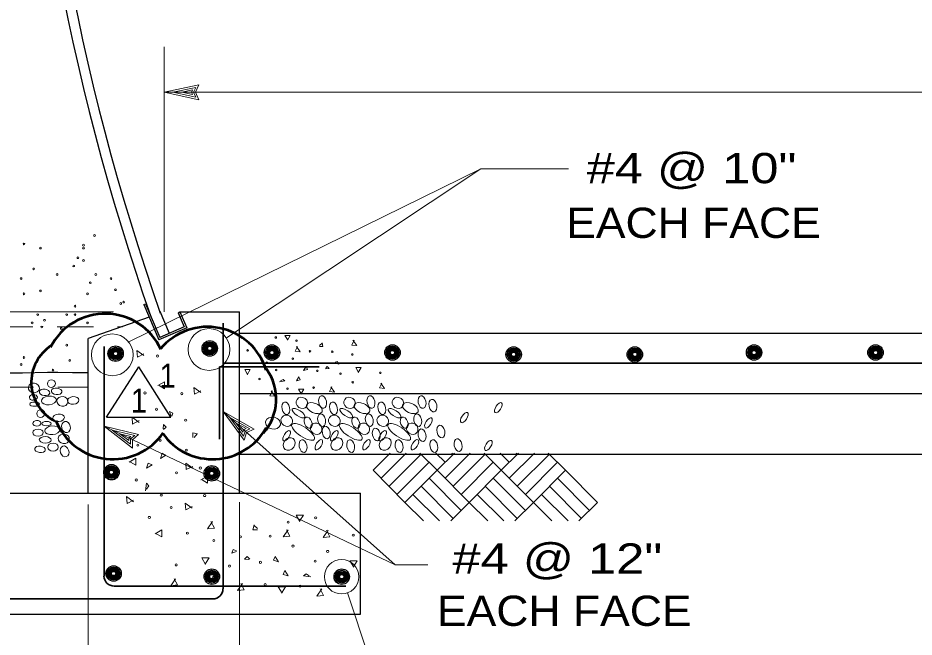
# Model space of a CAD drawing. Extents: x -24.3 to 17.7, y -17.6 to 12.4.
# Drawn here: x -16.992 to -13.287, y -12.611 to -10.053 of the extents above; entities that cross this region are included whole.
import ezdxf
from ezdxf.enums import TextEntityAlignment as Align

# ---------------------------------------------------------------- set-up
doc = ezdxf.new("R2010")
doc.units = 0
doc.header["$LTSCALE"] = 0.05
doc.linetypes.add('MEDIUM_DASHED', pattern=[4.5, 3, -1.5])
doc.layers.add('1', color=7, linetype='Continuous', lineweight=13)
doc.layers.add('2', color=7, linetype='Continuous', lineweight=13)

msp = doc.modelspace()

# ---------------------------------------------------------------- linework, layer by layer
at = {"layer": '1'}
for p, q in [((-16.38769, -11.2666), (-16.38769, -10.1726)), ((-16.38769, -10.3596), (-16.24369, -10.3286)), ((-16.38769, -10.3596), (-16.24369, -10.3906)), ((-16.35069, -10.3596), (-16.25669, -10.3396)), ((-16.35069, -10.3596), (-16.25669, -10.3796)), ((-16.31469, -10.3596), (-16.26969, -10.3496)), ((-16.31469, -10.3596), (-16.26969, -10.3686)), ((-16.26969, -10.3496), (-16.27369, -10.3596)), ((-16.27369, -10.3596), (-16.26969, -10.3686)), ((-16.25669, -10.3396), (-16.26569, -10.3596)), ((-16.26569, -10.3596), (-16.25669, -10.3796)), ((-15.07769, -10.6756), (-16.53369, -11.3916)), ((-15.07769, -10.6756), (-16.12969, -11.3746)), ((-15.07769, -10.6756), (-14.71569, -10.6756)), ((-16.59669, -11.2666), (-18.65469, -11.2666)), ((-15.43269, -12.3126), (-16.14369, -11.6786)), ((-16.14369, -11.6786), (-16.01569, -11.7516)), ((-16.14369, -11.6786), (-16.05669, -11.7976)), ((-16.11569, -11.7036), (-16.03269, -11.7506)), ((-16.11569, -11.7036), (-16.05969, -11.7806)), ((-15.43269, -12.3126), (-16.63569, -11.7396)), ((-16.63569, -11.7396), (-16.49269, -11.7736)), ((-16.63569, -11.7396), (-16.51869, -11.8296)), ((-16.08969, -11.7276), (-16.06169, -11.7636)), ((-16.08969, -11.7276), (-16.04869, -11.7496)), ((-16.60269, -11.7556), (-16.50869, -11.7776)), ((-16.60269, -11.7556), (-16.52569, -11.8136)), ((-16.56969, -11.7706), (-16.53269, -11.7986)), ((-16.56969, -11.7706), (-16.52469, -11.7816)), ((-16.50869, -11.7776), (-16.52569, -11.7916)), ((-16.05869, -11.7546), (-16.06169, -11.7636)), ((-16.05269, -11.7596), (-16.05969, -11.7806)), ((-16.04869, -11.7496), (-16.05869, -11.7546)), ((-16.03269, -11.7506), (-16.05269, -11.7596)), ((-16.52469, -11.7816), (-16.53269, -11.7886)), ((-16.53269, -11.7886), (-16.53269, -11.7986)), ((-16.52569, -11.7916), (-16.52569, -11.8136)), ((-15.52369, -11.9216), (-15.45269, -11.8506)), ((-15.49069, -11.9546), (-15.38669, -11.8506)), ((-15.25869, -11.9216), (-15.32969, -11.8506)), ((-15.22569, -11.8886), (-15.26369, -11.8506)), ((-15.25869, -11.9216), (-15.18769, -11.8506)), ((-15.25869, -11.9216), (-15.18769, -11.8506)), ((-15.22569, -11.9546), (-15.12169, -11.8506)), ((-15.19269, -11.8556), (-15.19769, -11.8506)), ((-14.99369, -11.9216), (-15.06469, -11.8506)), ((-14.96069, -11.8886), (-14.99869, -11.8506)), ((-14.99369, -11.9216), (-14.92269, -11.8506)), ((-14.96069, -11.9546), (-14.85569, -11.8506)), ((-14.92769, -11.8556), (-14.93169, -11.8506)), ((-14.72869, -11.9216), (-14.79969, -11.8506)), ((-15.45769, -11.9876), (-15.32469, -11.8556)), ((-15.42469, -12.0216), (-15.29169, -11.8886)), ((-15.19269, -11.9876), (-15.05969, -11.8556)), ((-15.15969, -12.0216), (-15.02669, -11.8886)), ((-14.92769, -11.9876), (-14.79469, -11.8556)), ((-14.89369, -12.0216), (-14.76169, -11.8886)), ((-15.39169, -12.0546), (-15.25869, -11.9216)), ((-15.12569, -12.0546), (-15.25869, -11.9216)), ((-15.12569, -12.0546), (-14.99369, -11.9216)), ((-14.86069, -12.0546), (-14.72869, -11.9216)), ((-14.59569, -12.0546), (-14.72869, -11.9216)), ((-15.15969, -12.0876), (-15.29169, -11.9546)), ((-14.89369, -12.0876), (-15.02669, -11.9546)), ((-14.62869, -12.0876), (-14.76169, -11.9546)), ((-15.19269, -12.1206), (-15.32469, -11.9876)), ((-14.92769, -12.1206), (-15.05969, -11.9876)), ((-14.66169, -12.1206), (-14.79469, -11.9876)), ((-15.24869, -12.1306), (-15.35869, -12.0216)), ((-14.98369, -12.1306), (-15.09269, -12.0216)), ((-14.71769, -12.1306), (-14.82769, -12.0216)), ((-16.70069, -13.6816), (-16.70069, -12.0626)), ((-16.07569, -14.4956), (-16.07569, -12.0536)), ((-15.20269, -12.1306), (-15.12569, -12.0546)), ((-15.04969, -12.1306), (-15.12569, -12.0546)), ((-14.93769, -12.1306), (-14.86069, -12.0546)), ((-14.67269, -12.1306), (-14.59569, -12.0546)), ((-15.43269, -12.3126), (-15.29669, -12.3126)), ((-15.39869, -13.1156), (-15.62969, -12.4286))]:
    msp.add_line(p, q, dxfattribs=at)
at = {"layer": '1', "lineweight": 25}
for p, q in [((-16.47169, -11.2366), (-16.46469, -11.2336)), ((-16.47169, -11.2366), (-16.40869, -11.3826)), ((-16.46469, -11.2336), (-16.40469, -11.3726)), ((-16.44969, -11.2886), (-16.70069, -11.3776)), ((-16.40569, -11.2646), (-16.36669, -11.3556)), ((-16.32969, -11.2706), (-16.32269, -11.2666)), ((-16.32369, -11.2666), (-16.07569, -11.2666)), ((-16.32269, -11.2666), (-16.29369, -11.3326)), ((-16.07569, -12.0166), (-16.07569, -11.2666)), ((-16.29369, -11.3326), (-16.40869, -11.3826)), ((-16.07569, -11.3546), (-3.74269, -11.3546)), ((-16.70069, -12.0166), (-16.70069, -11.3776)), ((-16.62493, -11.70276), (-16.49193, -11.49376)), ((-16.35893, -11.70276), (-16.49193, -11.49376)), ((-16.07569, -11.6046), (-3.74269, -11.6046)), ((-16.62493, -11.70276), (-16.35893, -11.70276)), ((-16.07569, -11.8546), (-3.74269, -11.8546)), ((-17.20069, -12.0166), (-15.57569, -12.0166))]:
    msp.add_line(p, q, dxfattribs=at)
at = {"layer": '1', "linetype": 'MEDIUM_DASHED'}
for p, q in [((-17.57969, -11.3286), (-16.55969, -11.3286)), ((-17.57669, -11.5786), (-16.69969, -11.5786))]:
    msp.add_line(p, q, dxfattribs=at)
at = {"layer": '1', "lineweight": 35}
for p, q in [((-16.14369, -12.4116), (-16.14369, -11.3136)), ((-16.63569, -12.3586), (-16.63569, -11.4106)), ((-16.13916, -11.4796), (-9.96569, -11.4796)), ((-15.74671, -11.49478), (-16.15797, -11.49478)), ((-16.15797, -11.79276), (-16.15797, -11.49478)), ((-15.63669, -12.4006), (-16.59369, -12.4006)), ((-16.18569, -12.4526), (-17.11869, -12.4526))]:
    msp.add_line(p, q, dxfattribs=at)
at = {"layer": '1'}
for points in [[(-16.24369, -10.3286), (-16.25769, -10.3596), (-16.24369, -10.3906)], [(-16.38769, -10.3596), (-9.90869, -10.3596), (-3.42969, -10.3596), (-3.57369, -10.3906)], [(-16.49269, -11.7736), (-16.51869, -11.7956), (-16.51869, -11.8296)], [(-16.01569, -11.7516), (-16.04669, -11.7656), (-16.05669, -11.7976)], [(-14.78469, -12.1306), (-14.99369, -11.9216), (-14.92269, -11.8506)], [(-15.31469, -12.1306), (-15.39169, -12.0546), (-15.52369, -11.9216)]]:
    msp.add_lwpolyline(points, dxfattribs=at)
at = {"layer": '1', "lineweight": 25}
for points in [[(-16.32969, -11.2706), (-16.30469, -11.3286), (-16.40469, -11.3726)], [(-17.06169, -11.5196), (-16.97269, -11.5196), (-16.86869, -11.5156), (-16.82669, -11.5156), (-16.76669, -11.5176), (-16.70069, -11.5176)], [(-17.20069, -12.5166), (-15.57569, -12.5166), (-15.57569, -12.0166)]]:
    msp.add_lwpolyline(points, dxfattribs=at)
at = {"layer": '1'}
for centre, radius in [((-16.67469, -10.9516), 0.00361), ((-16.96669, -10.9866), 0.00361), ((-16.89869, -11.0036), 0.00361), ((-16.72069, -10.9916), 0.00361), ((-16.72069, -11.0036), 0.00361), ((-16.76069, -11.0776), 0.00361), ((-16.74369, -11.0436), 0.00361), ((-16.72069, -11.0546), 0.00361), ((-16.92669, -11.0896), 0.00361), ((-16.82969, -11.1126), 0.00361), ((-16.66969, -11.1126), 0.00361), ((-16.97869, -11.1296), 0.00361), ((-16.69269, -11.1466), 0.00361), ((-16.60669, -11.1296), 0.00361), ((-16.89869, -11.1806), 0.00361), ((-16.58869, -11.1756), 0.00361), ((-16.96669, -11.1926), 0.00361), ((-16.70369, -11.1926), 0.00361), ((-16.55469, -11.2266), 0.00361), ((-16.75569, -11.2436), 0.00361), ((-16.56669, -11.2326), 0.00361), ((-16.90969, -11.2786), 0.00361), ((-16.88169, -11.3016), 0.00361), ((-16.78969, -11.2786), 0.00361), ((-16.75569, -11.2786), 0.00361), ((-16.93269, -11.3126), 0.00361), ((-16.89269, -11.3296), 0.00361), ((-16.81269, -11.3356), 0.00361), ((-16.70369, -11.3126), 0.00361), ((-16.60169, -11.4446), 0.08613), ((-16.20169, -11.4226), 0.08613), ((-16.78969, -11.4046), 0.00361), ((-16.97869, -11.4846), 0.00361), ((-16.96669, -11.4556), 0.00361), ((-16.77769, -11.4676), 0.00361), ((-16.84669, -11.5076), 0.00361), ((-15.65369, -12.3616), 0.0712)]:
    msp.add_circle(centre, radius, dxfattribs=at)
at = {"layer": '1', "lineweight": 25}
for centre, radius in [((-16.58797, -11.43969), 0.0319), ((-16.19865, -11.41821), 0.0319), ((-16.19865, -11.41821), 0.02658), ((-16.19865, -11.41821), 0.02215), ((-16.19865, -11.41821), 0.01846), ((-16.19865, -11.41821), 0.01538), ((-16.19865, -11.41821), 0.01282), ((-16.19865, -11.41821), 0.01068), ((-16.19865, -11.41821), 0.0089), ((-15.94149, -11.43513), 0.0319), ((-15.94149, -11.43513), 0.02658), ((-15.44351, -11.43513), 0.0319), ((-15.44351, -11.43513), 0.02658), ((-13.94856, -11.43513), 0.0319), ((-13.94856, -11.43513), 0.02658), ((-13.44657, -11.43513), 0.0319), ((-13.44657, -11.43513), 0.02658), ((-16.58797, -11.43969), 0.02658), ((-16.58797, -11.43969), 0.02215), ((-16.58797, -11.43969), 0.01846), ((-16.58797, -11.43969), 0.01538), ((-16.58797, -11.43969), 0.01282), ((-16.58797, -11.43969), 0.01068), ((-16.58797, -11.43969), 0.0089), ((-15.94149, -11.43513), 0.02215), ((-15.94149, -11.43513), 0.01846), ((-15.94149, -11.43513), 0.01538), ((-15.94149, -11.43513), 0.01282), ((-15.94149, -11.43513), 0.01068), ((-15.94149, -11.43513), 0.0089), ((-15.44351, -11.43513), 0.02215), ((-15.44351, -11.43513), 0.01846), ((-15.44351, -11.43513), 0.01538), ((-15.44351, -11.43513), 0.01282), ((-15.44351, -11.43513), 0.01068), ((-15.44351, -11.43513), 0.0089), ((-14.94253, -11.44313), 0.0319), ((-14.94253, -11.44313), 0.02658), ((-14.94253, -11.44313), 0.02215), ((-14.94253, -11.44313), 0.01846), ((-14.94253, -11.44313), 0.01538), ((-14.94253, -11.44313), 0.01282), ((-14.94253, -11.44313), 0.01068), ((-14.94253, -11.44313), 0.0089), ((-14.44154, -11.44313), 0.0319), ((-14.44154, -11.44313), 0.02658), ((-14.44154, -11.44313), 0.02215), ((-14.44154, -11.44313), 0.01846), ((-14.44154, -11.44313), 0.01538), ((-14.44154, -11.44313), 0.01282), ((-14.44154, -11.44313), 0.01068), ((-14.44154, -11.44313), 0.0089), ((-13.94856, -11.43513), 0.02215), ((-13.94856, -11.43513), 0.01846), ((-13.94856, -11.43513), 0.01538), ((-13.94856, -11.43513), 0.01282), ((-13.94856, -11.43513), 0.01068), ((-13.94856, -11.43513), 0.0089), ((-13.44657, -11.43513), 0.02215), ((-13.44657, -11.43513), 0.01846), ((-13.44657, -11.43513), 0.01538), ((-13.44657, -11.43513), 0.01282), ((-13.44657, -11.43513), 0.01068), ((-13.44657, -11.43513), 0.0089), ((-16.60497, -11.92969), 0.0319), ((-16.60497, -11.92969), 0.02658), ((-16.60497, -11.92969), 0.02215), ((-16.60497, -11.92969), 0.01846), ((-16.60497, -11.92969), 0.01538), ((-16.60497, -11.92969), 0.01282), ((-16.60497, -11.92969), 0.01068), ((-16.60497, -11.92969), 0.0089), ((-16.19032, -11.93444), 0.0319), ((-16.19032, -11.93444), 0.02658), ((-16.19032, -11.93444), 0.02215), ((-16.19032, -11.93444), 0.01846), ((-16.19032, -11.93444), 0.01538), ((-16.19032, -11.93444), 0.01282), ((-16.19032, -11.93444), 0.01068), ((-16.19032, -11.93444), 0.0089), ((-16.59622, -12.34818), 0.0319), ((-16.59622, -12.34818), 0.02658), ((-16.59622, -12.34818), 0.02215), ((-16.59622, -12.34818), 0.01846), ((-16.59622, -12.34818), 0.01538), ((-16.59622, -12.34818), 0.01282), ((-16.19007, -12.3611), 0.0319), ((-16.19007, -12.3611), 0.02658), ((-15.65309, -12.36135), 0.0319), ((-15.65309, -12.36135), 0.02658), ((-16.59622, -12.34818), 0.01068), ((-16.59622, -12.34818), 0.0089), ((-16.19007, -12.3611), 0.02215), ((-16.19007, -12.3611), 0.01846), ((-16.19007, -12.3611), 0.01538), ((-16.19007, -12.3611), 0.01282), ((-16.19007, -12.3611), 0.01068), ((-16.19007, -12.3611), 0.0089), ((-15.65309, -12.36135), 0.02215), ((-15.65309, -12.36135), 0.01846), ((-15.65309, -12.36135), 0.01538), ((-15.65309, -12.36135), 0.01282), ((-15.65309, -12.36135), 0.01068), ((-15.65309, -12.36135), 0.0089)]:
    msp.add_circle(centre, radius, dxfattribs=at)
for radius in [9.74984, 9.70818]:
    msp.add_arc((-7.24244, -8.05836), radius, 180.86487, 199.33073, dxfattribs=at)
at = {"layer": '1', "lineweight": 53}
for centre, radius, start, end in [((-16.63089, -11.52803), 0.25334, 24.55974, 152.92582), ((-16.20764, -11.58231), 0.25334, 16.99373, 140.21229), ((-16.75642, -11.55812), 0.18009, 122.74739, 242.84867), ((-16.13663, -11.62787), 0.21291, 318.5024, 35.87306), ((-16.59928, -11.62262), 0.25334, 201.68598, 325.30294), ((-16.18689, -11.62262), 0.25334, 215.44791, 330.66798)]:
    msp.add_arc(centre, radius, start, end, dxfattribs=at)
at = {"layer": '1', "lineweight": 35}
for centre, start, end in [((-16.59416, -12.35863), 180, 270), ((-16.18575, -12.41133), 270, 0)]:
    msp.add_arc(centre, 0.04167, start, end, dxfattribs=at)
at = {"layer": '1'}
for centre, major_axis, ratio in [((-16.85327, -11.56354), (0.01537, 0.00658), 0.943549), ((-16.92573, -11.58115), (0.02279, -0.0031), 0.872178), ((-16.88127, -11.59977), (0.02175, -0.0031), 0.60385), ((-16.83156, -11.59565), (0.02175, -0.0031), 0.60385), ((-16.92783, -11.62052), (0.01656, 0.00102), 0.695424), ((-16.86366, -11.63294), (0.03106, 0.0031), 0.576005), ((-16.80773, -11.63706), (0.02279, -0.0031), 0.872178), ((-16.76323, -11.63294), (-0.024, -0.00161), 0.646571), ((-15.81769, -11.6431), (-0.02021, 0.0142), 0.915279), ((-15.73219, -11.6396), (-0.0055, 0.026), 0.599528), ((-15.62069, -11.6431), (-0.02021, 0.0142), 0.915279), ((-15.53219, -11.6396), (-0.0055, 0.026), 0.599528), ((-15.42069, -11.6431), (-0.02021, 0.0142), 0.915279), ((-15.32119, -11.6396), (-0.0055, 0.026), 0.599528), ((-15.27619, -11.6546), (-0.0055, 0.026), 0.599528), ((-16.92264, -11.64846), (0.01967, 0), 0.453554), ((-15.88419, -11.6656), (-0.0055, 0.026), 0.599528), ((-15.83169, -11.6856), (-0.026, 0.017), 0.365968), ((-15.76619, -11.6646), (-0.0315, 0.015), 0.562188), ((-15.68719, -11.6656), (-0.0055, 0.026), 0.599528), ((-15.63469, -11.6856), (-0.026, 0.017), 0.365968), ((-15.56919, -11.6646), (-0.0315, 0.015), 0.562188), ((-15.48719, -11.6656), (-0.0055, 0.026), 0.599528), ((-15.43469, -11.6856), (-0.026, 0.017), 0.365968), ((-15.36919, -11.6646), (-0.0315, 0.015), 0.562188), ((-15.00569, -11.6631), (0.013, 0.0205), 0.445558), ((-16.89718, -11.68714), (0.01537, 0.00658), 0.943549), ((-16.82369, -11.70474), (-0.024, -0.00161), 0.646571), ((-15.93719, -11.7266), (-0.03038, 0.00696), 0.790099), ((-15.88069, -11.7171), (-0.02021, 0.0142), 0.915279), ((-15.79169, -11.7251), (-0.009, 0.0225), 0.615421), ((-15.73619, -11.7146), (-0.0055, 0.026), 0.599528), ((-15.68369, -11.7171), (-0.02021, 0.0142), 0.915279), ((-15.59469, -11.7251), (-0.009, 0.0225), 0.615421), ((-15.53919, -11.7146), (-0.0055, 0.026), 0.599528), ((-15.48369, -11.7171), (-0.02021, 0.0142), 0.915279), ((-15.39469, -11.7251), (-0.009, 0.0225), 0.615421), ((-15.33919, -11.7146), (-0.0055, 0.026), 0.599528), ((-15.29469, -11.7261), (0.013, 0.0205), 0.445558), ((-15.14669, -11.7041), (0.013, 0.0205), 0.445558), ((-16.91375, -11.72753), (0.01656, 0.00102), 0.695424), ((-16.87339, -11.72855), (0.01967, 0), 0.453554), ((-16.84958, -11.75653), (0.03106, 0.0031), 0.576005), ((-16.79262, -11.74305), (0.00519, -0.02279), 0.773526), ((-15.81269, -11.7631), (-0.04615, 0.03077), 0.357541), ((-15.75869, -11.7501), (-0.02021, 0.0142), 0.915279), ((-15.71719, -11.7656), (-0.0055, 0.026), 0.599528), ((-15.61569, -11.7631), (-0.04615, 0.03077), 0.357541), ((-15.56169, -11.7501), (-0.02021, 0.0142), 0.915279), ((-15.41569, -11.7631), (-0.04615, 0.03077), 0.357541), ((-15.36169, -11.7501), (-0.02021, 0.0142), 0.915279), ((-15.24319, -11.7616), (-0.0055, 0.026), 0.599528), ((-16.90858, -11.76585), (0.02173, 0), 0.668043), ((-16.80194, -11.7917), (0.02279, -0.0031), 0.872178), ((-15.88069, -11.7791), (0.013, 0.0205), 0.445558), ((-15.68369, -11.7791), (0.013, 0.0205), 0.445558), ((-15.51019, -11.7736), (-0.0055, 0.026), 0.599528), ((-15.48369, -11.7791), (0.013, 0.0205), 0.445558), ((-15.32119, -11.7766), (-0.0055, 0.026), 0.599528), ((-16.87856, -11.79584), (0.02483, -0.00104), 0.540552), ((-16.84646, -11.82589), (0.02173, 0), 0.771092), ((-15.87019, -11.8131), (0.0165, 0.0225), 0.822116), ((-15.81319, -11.8216), (-0.0055, 0.026), 0.599528), ((-15.74769, -11.8161), (0.013, 0.0205), 0.445558), ((-15.67319, -11.8131), (0.0165, 0.0225), 0.822116), ((-15.61619, -11.8216), (-0.0055, 0.026), 0.599528), ((-15.55069, -11.8161), (0.013, 0.0205), 0.445558), ((-15.47319, -11.8131), (0.0165, 0.0225), 0.822116), ((-15.41619, -11.8216), (-0.0055, 0.026), 0.599528), ((-15.35069, -11.8161), (0.013, 0.0205), 0.445558), ((-15.27219, -11.8216), (-0.0055, 0.026), 0.599528), ((-15.17219, -11.8176), (-0.0055, 0.026), 0.599528), ((-15.04669, -11.8191), (0.013, 0.0205), 0.445558), ((-16.90031, -11.8352), (0.02175, -0.0031), 0.60385), ((-16.79885, -11.84349), (0.00725, -0.02173), 0.776129)]:
    msp.add_ellipse(centre, major_axis=major_axis, ratio=ratio, dxfattribs=at)
at = {"layer": '2'}
for p, q in [((-15.74569, -11.4066), (-15.73469, -11.3966)), ((-16.26369, -11.7866), (-16.25069, -11.7706)), ((-16.00069, -12.1626), (-16.01569, -12.1496))]:
    msp.add_line(p, q, dxfattribs=at)
for points in [[(-15.87769, -11.3816), (-15.88769, -11.3646), (-15.86569, -11.3646), (-15.87769, -11.3846)], [(-15.73469, -11.3946), (-15.73069, -11.4096), (-15.74569, -11.4096)], [(-15.60169, -11.3846), (-15.61169, -11.4046), (-15.59069, -11.4066), (-15.60669, -11.3846)], [(-16.47069, -11.4406), (-16.49769, -11.4546), (-16.49969, -11.4266), (-16.47069, -11.4476)], [(-15.95969, -11.4116), (-15.96969, -11.4316), (-15.94969, -11.4336), (-15.96469, -11.4116)], [(-15.83569, -11.4096), (-15.84569, -11.4296), (-15.82469, -11.4316), (-15.84069, -11.4096)], [(-15.68069, -11.4756), (-15.67069, -11.4716), (-15.66569, -11.4826), (-15.68069, -11.4776)], [(-16.04369, -11.5226), (-16.05369, -11.5056), (-16.03169, -11.5056), (-16.04369, -11.5266)], [(-15.72069, -11.5006), (-15.71369, -11.4926), (-15.70569, -11.5006), (-15.71869, -11.5026)], [(-15.58469, -11.5146), (-15.59469, -11.4976), (-15.57269, -11.4976), (-15.58469, -11.5176)], [(-16.40769, -11.5716), (-16.38569, -11.5846), (-16.38569, -11.5556), (-16.41269, -11.5716)], [(-15.90569, -11.5526), (-15.89569, -11.5466), (-15.88769, -11.5526), (-15.91069, -11.5566)], [(-16.23569, -11.5936), (-16.26169, -11.6066), (-16.26469, -11.5796), (-16.23569, -11.6006)], [(-15.93969, -11.5936), (-15.94969, -11.6136), (-15.92969, -11.6156), (-15.94469, -11.5936)], [(-15.82169, -11.6036), (-15.83169, -11.5866), (-15.80969, -11.5866), (-15.82169, -11.6066)], [(-15.69369, -11.5766), (-15.70369, -11.5966), (-15.68369, -11.5986), (-15.69869, -11.5766)], [(-15.48669, -11.5616), (-15.49669, -11.5816), (-15.47669, -11.5836), (-15.49169, -11.5616)], [(-16.49069, -11.7166), (-16.51769, -11.7306), (-16.51969, -11.7026), (-16.49069, -11.7236)], [(-16.35569, -11.6986), (-16.35169, -11.6856), (-16.36569, -11.6786), (-16.35869, -11.6986)], [(-16.38969, -11.7526), (-16.37869, -11.7436), (-16.38969, -11.7326), (-16.39169, -11.7506)], [(-16.24869, -11.7706), (-16.26869, -11.7666), (-16.26869, -11.7866)], [(-16.52669, -11.8876), (-16.50369, -11.9006), (-16.50369, -11.8716), (-16.53169, -11.8876)], [(-16.26869, -11.9056), (-16.29569, -11.9186), (-16.29769, -11.8916), (-16.26869, -11.9126)], [(-16.23069, -11.9616), (-16.20769, -11.9746), (-16.20769, -11.9456), (-16.23569, -11.9616)], [(-16.45969, -11.9996), (-16.45069, -11.9866), (-16.45969, -11.9746), (-16.46369, -12.0066)], [(-16.51369, -12.0446), (-16.53969, -12.0586), (-16.54269, -12.0306), (-16.51369, -12.0516)], [(-16.27169, -12.0716), (-16.29769, -12.0846), (-16.30069, -12.0576), (-16.27169, -12.0786)], [(-15.82569, -12.1296), (-15.81169, -12.1066), (-15.84169, -12.1066), (-15.82569, -12.1336)], [(-16.19369, -12.1336), (-16.17969, -12.1606), (-16.20769, -12.1636), (-16.18669, -12.1336)], [(-16.01569, -12.1476), (-16.02069, -12.1676), (-16.00069, -12.1676)], [(-16.41969, -12.1836), (-16.39669, -12.1966), (-16.39669, -12.1676), (-16.42369, -12.1836)], [(-15.88169, -12.1676), (-15.86769, -12.1936), (-15.89569, -12.1966), (-15.87469, -12.1676)], [(-15.71569, -12.1696), (-15.70169, -12.1966), (-15.72969, -12.1996), (-15.70869, -12.1696)], [(-16.08769, -12.2546), (-16.10169, -12.2496), (-16.10769, -12.2636), (-16.08769, -12.2576)], [(-16.21569, -12.3066), (-16.20169, -12.2836), (-16.23169, -12.2836), (-16.21569, -12.3116)], [(-16.03369, -12.2886), (-16.04369, -12.2776), (-16.05469, -12.2886), (-16.03669, -12.2906)], [(-15.60369, -12.3176), (-15.58969, -12.2956), (-15.61969, -12.2956), (-15.60369, -12.3226)], [(-16.34569, -12.3696), (-16.33269, -12.3956), (-16.35969, -12.3986), (-16.33969, -12.3696)], [(-15.78769, -12.3576), (-15.80069, -12.3496), (-15.81169, -12.3576), (-15.78069, -12.3626)], [(-16.06969, -12.3896), (-16.05669, -12.4156), (-16.08369, -12.4186), (-16.06369, -12.3896)], [(-15.89969, -12.4256), (-15.88569, -12.4026), (-15.91569, -12.4026), (-15.89969, -12.4296)], [(-15.74169, -12.4116), (-15.72869, -12.4386), (-15.75569, -12.4416), (-15.73569, -12.4116)]]:
    msp.add_lwpolyline(points, dxfattribs=at)
for points in [[(-15.81069, -11.5096), (-15.80069, -11.4926), (-15.79469, -11.5046)], [(-15.84069, -11.5526), (-15.83069, -11.5356), (-15.82469, -11.5476)], [(-16.40169, -11.8726), (-16.37969, -11.8586), (-16.39569, -11.8516)], [(-16.45969, -11.9126), (-16.43669, -11.8986), (-16.45269, -11.8916)], [(-15.91469, -12.3006), (-15.92769, -12.2776), (-15.93569, -12.2936)], [(-15.87469, -12.3576), (-15.88769, -12.3356), (-15.89569, -12.3516)]]:
    msp.add_lwpolyline(points, close=True, dxfattribs=at)
for centre, radius in [((-15.92574, -11.37289), 0.00325), ((-15.84024, -11.38639), 0.00325), ((-16.41442, -11.44964), 0.00433), ((-16.04224, -11.42639), 0.00325), ((-15.78474, -11.42989), 0.00325), ((-15.69224, -11.43189), 0.00325), ((-15.60974, -11.44339), 0.00325), ((-15.96274, -11.47689), 0.00325), ((-15.85524, -11.46039), 0.00325), ((-15.92424, -11.50739), 0.00325), ((-15.75424, -11.51089), 0.00325), ((-15.65824, -11.52239), 0.00325), ((-15.49324, -11.51889), 0.00325), ((-15.99324, -11.54439), 0.00325), ((-15.60774, -11.55789), 0.00325), ((-15.87724, -11.58489), 0.00325), ((-15.76924, -11.57989), 0.00325), ((-16.46642, -11.6023), 0.00433), ((-16.31375, -11.60497), 0.00433), ((-16.41908, -11.66964), 0.00433), ((-16.29842, -11.71497), 0.00433), ((-16.49575, -11.81763), 0.00433), ((-16.40375, -11.79763), 0.00433), ((-16.29575, -11.8383), 0.00433), ((-16.23775, -11.9123), 0.00433), ((-16.50242, -11.96163), 0.00433), ((-16.33642, -11.9323), 0.00433), ((-16.39908, -12.0243), 0.00433), ((-16.21975, -12.0263), 0.00433), ((-16.35842, -12.07563), 0.00433), ((-16.44842, -12.1163), 0.00433), ((-15.87472, -12.13613), 0.00433), ((-15.76072, -12.11813), 0.00433), ((-16.29109, -12.18163), 0.00433), ((-15.60539, -12.18946), 0.00433), ((-16.18205, -12.21213), 0.00433), ((-16.07205, -12.19679), 0.00433), ((-15.94872, -12.19413), 0.00433), ((-15.85472, -12.23479), 0.00433), ((-15.71139, -12.25679), 0.00433), ((-15.98938, -12.30213), 0.00433), ((-15.76272, -12.29746), 0.00433), ((-16.33738, -12.31279), 0.00433), ((-16.11738, -12.31746), 0.00433), ((-16.18471, -12.36479), 0.00433), ((-15.67072, -12.34679), 0.00433), ((-15.96938, -12.39412), 0.00433), ((-15.82538, -12.40079), 0.00433)]:
    msp.add_circle(centre, radius, dxfattribs=at)

# ---------------------------------------------------------------- texts
at = {"layer": '1', "width": 1.25}
msp.add_text('#4 @ 10"', height=0.125, dxfattribs=at).set_placement((-14.64069, -10.7356))
at = {"layer": '1'}
for s, height, width, p in [('EACH FACE', 0.125, 1.1, (-14.19919, -10.9616)), ('1', 0.1, 0.9, (-16.37259, -11.58076)), ('1', 0.1, 0.9, (-16.49159, -11.68376)), ('#4 @ 12"', 0.125, 1.25, (-14.76169, -12.3486)), ('EACH FACE', 0.125, 1.1, (-14.73319, -12.5646))]:
    msp.add_text(s, height=height, dxfattribs=dict(at, width=width)).set_placement(p, align=Align.CENTER)

doc.saveas('drawing.dxf')
